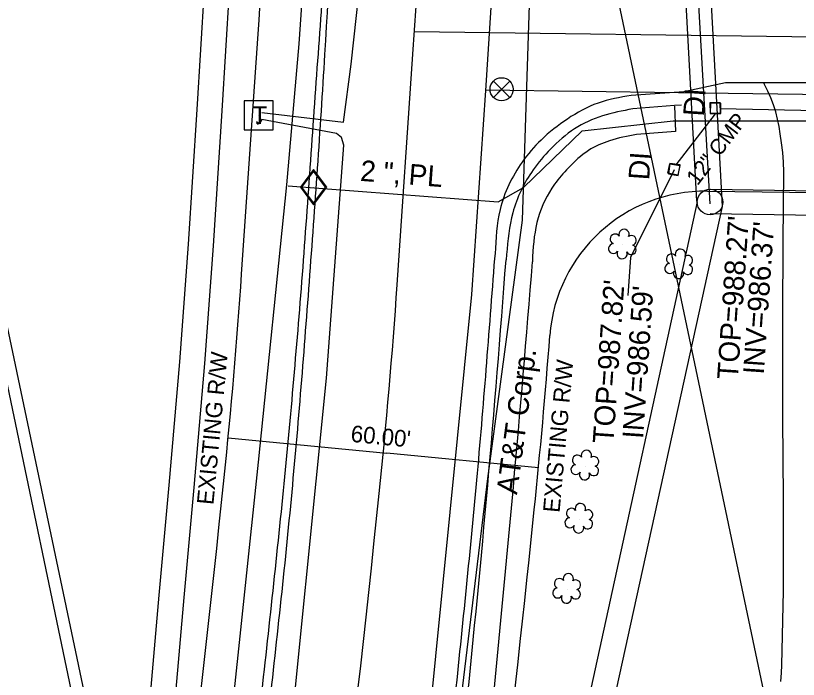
# Model space of a CAD drawing. Extents: x 1614427 to 1617186, y 896524 to 905462.
# Drawn here: x 1616608.8 to 1616759.4, y 901942.1 to 902069.8 of the extents above; entities that cross this region are included whole.
import ezdxf

# ---------------------------------------------------------------- set-up
doc = ezdxf.new("R2010")
doc.units = 0
for name, color, linetype in [('Exist Horizontal Alignment', 7, 'Continuous'), ('Exist Right of Way Line', 7, 'Continuous'), ('Exist Right of Way Line Text', 7, 'Continuous'), ('Exist Right of Way Width CELL', 7, 'Continuous'), ('Exist Roads Curbs', 7, 'Continuous'), ('Exist Roads EOP', 7, 'Continuous'), ('Exist Roads EOP Other', 7, 'Continuous'), ('Exist Roads EOT', 7, 'Continuous'), ('Exist Structure Minor Drop Inlet', 7, 'Continuous'), ('Exist Structure Minor Drop Inlet Leader', 7, 'Continuous'), ('Exist Structure Minor Drop Inlet Text', 7, 'Continuous'), ('Exist Structure Minor Drop Inlet Top Elevation', 7, 'Continuous'), ('Exist Structure Minor Pipes CMP 12 Inch', 7, 'Continuous'), ('Exist Structure Minor Pipes CMP 12 Inch Invert', 7, 'Continuous'), ('Exist Structure Minor Pipes CMP 12 Inch Text', 7, 'Continuous'), ('Exist Structure Minor Pipes RCP 12 Inch', 7, 'Continuous'), ('Exist Structure Minor Pipes RCP 12 Inch Invert', 7, 'Continuous'), ('Exist Utilities Gas UG Line SUE LOS B', 7, 'Continuous'), ('Exist Utilities Gas UG Line SUE LOS B Text', 7, 'Continuous'), ('Exist Utilities Gas Valve CELL', 7, 'Continuous'), ('Exist Utilities Other Pole CELL', 7, 'Continuous'), ('Exist Utilities Power UG Cable SUE LOS D', 7, 'Continuous'), ('Exist Utilities Telephone Pedestal CELL', 7, 'Continuous'), ('Exist Utilities Telephone UG Cable SUE LOS B', 7, 'Continuous'), ('Exist Utilities Telephone UG FO SUE LOS B', 7, 'Continuous'), ('Exist Utilities Telephone UG FO SUE LOS B Text', 7, 'Continuous'), ('Exist Utilities Telephone UG FO SUE LOS D', 7, 'Continuous'), ('Exist Utilities TV UG FO Cable SUE LOS D', 7, 'Continuous'), ('Exist Utilities Water UG Line SUE LOS B', 7, 'Continuous'), ('Exist Utilities Water Valve CELL', 7, 'Continuous'), ('Exist Vegetation Shrub CELL', 7, 'Continuous')]:
    doc.layers.add(name, color=color, linetype=linetype)

# ---------------------------------------------------------------- blocks, each defined once
blk = doc.blocks.new('EXIST UTILITIES WATER VALVE')
at = {"layer": 'Exist Utilities Water Valve CELL'}
blk.add_lwpolyline([(0.0315, 0.0315), (-0.0315, -0.0315), (0, 0), (0.0315, -0.0315), (-0.0315, 0.0315)], dxfattribs=at)
blk.add_circle((0, 0), 0.0445, dxfattribs=at)
blk = doc.blocks.new('EXIST UTILITIES GAS VALVE')
at = {"layer": 'Exist Utilities Gas Valve CELL'}
blk.add_line((0, 0), (0, 0), dxfattribs=at)
blk.add_lwpolyline([(0, 0.0683), (-0.0508, 0), (0, -0.0683), (0.0508, 0), (0, 0.0683)], dxfattribs=at)
blk.add_lwpolyline([(0.0458, 0), (0, 0.0615), (-0.0458, 0), (0, -0.0615)], close=True, dxfattribs=at)
blk = doc.blocks.new('EXIST UTILITIES TELEPHONE PEDESTAL')
at = {"layer": 'Exist Utilities Telephone Pedestal CELL'}
blk.add_line((0, 0), (0, 0), dxfattribs=at)
blk.add_lwpolyline([(-0.0545, -0.0565), (0.0574, -0.0565), (0.0574, 0.0554), (-0.0545, 0.0554), (-0.0545, -0.0565)], dxfattribs=at)
blk.add_text('T', height=0.0684, dxfattribs=at).set_placement((-0.0226, -0.0343))

msp = doc.modelspace()

# ---------------------------------------------------------------- linework, layer by layer
at = {"layer": 'Exist Horizontal Alignment'}
for p, q in [((1616685.54, 902066.8), (1616995.51, 902062.72)), ((1616682.21, 902018.06), (1616685.25, 902062.41)), ((1616677.74, 901968.22), (1616678.75, 901977.88))]:
    msp.add_line(p, q, dxfattribs=at)
for centre, radius, start, end in [((1614235.45, 902230.14), 2455.53, 356.08333, 2.98333), ((1615538.97, 902096.33), 1145.92, 354.06667, 356.08333), ((1613828.3, 902264.36), 2864.79, 348.01667, 354.06667)]:
    msp.add_arc(centre, radius, start, end, dxfattribs=at)
at = {"layer": 'Exist Right of Way Line'}
for p, q in [((1616010.65, 905462.23), (1616993.32, 900797.76)), ((1615887.44, 905426.15), (1616864.55, 900788.06)), ((1616652.28, 902020.11), (1616655.32, 902064.46)), ((1616741.9, 902036.05), (1616995.11, 902032.72)), ((1616647.9, 901971.32), (1616648.91, 901980.98)), ((1616707.58, 901965.12), (1616708.59, 901974.78))]:
    msp.add_line(p, q, dxfattribs=at)
for centre, radius, start, end in [((1614235.45, 902230.14), 2425.53, 356.08333, 2.98333), ((1616741.5, 902006.06), 30, 89.2466, 175.7066), ((1615538.97, 902096.33), 1115.92, 354.06667, 356.08333), ((1615538.97, 902096.33), 1175.92, 354.06667, 355.70658), ((1613828.3, 902264.36), 2834.79, 348.81938, 354.06667), ((1613828.3, 902264.36), 2894.79, 349.06983, 354.06667)]:
    msp.add_arc(centre, radius, start, end, dxfattribs=at)
at = {"layer": 'Exist Right of Way Width CELL'}
for p in [(1616649.67, 901988.6), (1616709.39, 901982.8)]:
    msp.add_line(p, (1616680.22, 901985.63), dxfattribs=at)
at = {"layer": 'Exist Roads Curbs'}
msp.add_line((1616703.26, 902023.89), (1616703.16, 902022.83), dxfattribs=at)
msp.add_lwpolyline([(1616736.91, 902052.58), (1616735.58, 902052.56), (1616727.54, 902051.89)], dxfattribs=at)
msp.add_ellipse((1613763.47, 902238.4), major_axis=(355.71, 2940.7), ratio=0.995075, start_param=4.729988, end_param=4.759334, dxfattribs=at)
msp.add_spline([(1616727.54, 902051.89), (1616721.72, 902050.55), (1616716.36, 902048.06), (1616711.73, 902044.16), (1616708.36, 902040.14), (1616704.47, 902031.9), (1616703.26, 902023.89)], degree=3, dxfattribs=at)
at = {"layer": 'Exist Roads EOP'}
msp.add_line((1616701.09, 902024.04), (1616700.93, 902023.09), dxfattribs=at)
msp.add_lwpolyline([(1616995.15, 902054.27), (1616961.48, 902054.78), (1616918.48, 902055.01), (1616876.42, 902055.6), (1616833.56, 902056.42), (1616793.91, 902056.9), (1616751.65, 902056.89), (1616745.38, 902056.89), (1616737.38, 902055.19), (1616727.24, 902054.46)], dxfattribs=at)
for points in [[(1616655.28, 901931.6), (1616660.06, 901975.76), (1616663.88, 902018.68), (1616667.04, 902062.5), (1616670.01, 902105.53), (1616671.54, 902149.52), (1616672.6, 902193.68), (1616673.08, 902239.26), (1616672.8, 902282.74), (1616671, 902328.37), (1616668.63, 902372.54), (1616666.77, 902402.14), (1616664.33, 902433.03)], [(1616727.24, 902054.46), (1616720.86, 902053.02), (1616714.96, 902049.94), (1616709.89, 902045.9), (1616706.27, 902041.66), (1616702, 902032.51), (1616701.09, 902024.04)], [(1616700.93, 902023.09), (1616697.48, 901980.45), (1616693.1, 901936.47), (1616691.15, 901917.39), (1616689.48, 901902.09), (1616684.13, 901861.58), (1616677.6, 901820.03), (1616673.54, 901794.89), (1616668.88, 901768.87), (1616663.9, 901741.21), (1616658.75, 901714.99)]]:
    msp.add_spline(points, degree=3, dxfattribs=at)
at = {"layer": 'Exist Roads EOP Other'}
msp.add_line((1616708.24, 902023.52), (1616708.26, 902022.46), dxfattribs=at)
for points in [[(1616612.82, 901802.9), (1616617.67, 901825.43), (1616622.38, 901847.22), (1616626.49, 901866.61), (1616627.92, 901872.98), (1616628.44, 901875.07), (1616628.88, 901877.18), (1616629.24, 901879.31), (1616629.52, 901881.45), (1616629.72, 901883.51), (1616630.6, 901891.66), (1616631.35, 901901.23), (1616633.18, 901919.93), (1616634.76, 901939.16), (1616636.44, 901958.33), (1616638.35, 901979.47), (1616640.39, 902003.25), (1616642.08, 902025.89), (1616643.74, 902051.78), (1616645.12, 902074.94)], [(1616617.51, 901801.89), (1616622.36, 901824.42), (1616627.07, 901846.22), (1616631.18, 901865.59), (1616632.59, 901871.88), (1616633.12, 901874.01), (1616633.59, 901876.29), (1616633.98, 901878.59), (1616634.29, 901880.9), (1616634.5, 901883.02), (1616635.38, 901891.22), (1616636.14, 901900.81), (1616637.96, 901919.5), (1616639.54, 901938.75), (1616641.22, 901957.9), (1616643.14, 901979.05), (1616645.17, 902002.87), (1616646.87, 902025.55), (1616648.53, 902051.49), (1616649.92, 902074.68)], [(1616756.03, 901941.69), (1616756.17, 901943.36), (1616756.23, 901944.88), (1616756.53, 901959.19), (1616756.57, 901976.99), (1616756.44, 901992.33), (1616756.4, 902011.96), (1616756.5, 902026.37), (1616756.64, 902039.75), (1616756.57, 902041.62), (1616756.42, 902043.49), (1616756.19, 902045.34), (1616755.89, 902047.09), (1616755.7, 902048.51), (1616755.43, 902049.91), (1616755.07, 902051.3), (1616754.65, 902052.66), (1616754.14, 902054), (1616753.57, 902055.31), (1616752.92, 902056.58), (1616752.82, 902056.77)], [(1616735.56, 902052.4), (1616735.79, 902047.54), (1616728.27, 902046.98)]]:
    msp.add_lwpolyline(points, dxfattribs=at)
msp.add_ellipse((1612721.96, 902335.52), major_axis=(418.09, 4102.81), ratio=0.969558, start_param=4.713779, end_param=4.734862, dxfattribs=at)
msp.add_spline([(1616728.27, 902046.98), (1616723.09, 902045.76), (1616719.03, 902043.88), (1616715.16, 902040.56), (1616712.51, 902037.38), (1616709.33, 902030.9), (1616708.24, 902023.52)], degree=3, dxfattribs=at)
at = {"layer": 'Exist Roads EOT'}
msp.add_spline([(1616657.03, 901931.53), (1616661.72, 901975.47), (1616665.32, 902018.62), (1616668.31, 902062.36), (1616670.59, 902105.52), (1616672.4, 902149.47), (1616673.48, 902193.66), (1616673.75, 902239.27), (1616673.47, 902282.77), (1616672.23, 902328.42), (1616670.01, 902372.56), (1616668.01, 902402.36), (1616665.45, 902433.28)], degree=3, dxfattribs=at)
at = {"layer": 'Exist Structure Minor Drop Inlet'}
for points in [[(1616744.34, 902051.01), (1616742.48, 902050.98), (1616742.45, 902053.11), (1616744.31, 902053.13)], [(1616736.24, 902039.14), (1616734.32, 902039.51), (1616734.66, 902041.33), (1616736.59, 902040.97)]]:
    msp.add_lwpolyline(points, close=True, dxfattribs=at)
for points in [[(1616744.49, 902052.96), (1616742.48, 902052.99), (1616742.45, 902051), (1616744.51, 902051.03), (1616744.49, 902052.96)], [(1616736.65, 902041.11), (1616734.69, 902041.41), (1616734.44, 902039.42), (1616736.31, 902039.1), (1616736.65, 902041.11)]]:
    msp.add_lwpolyline(points, dxfattribs=at)
at = {"layer": 'Exist Structure Minor Drop Inlet Leader'}
msp.add_lwpolyline([(1616735.52, 902040.19), (1616727.1, 902023.27), (1616726.59, 902015.96)], dxfattribs=at)
at = {"layer": 'Exist Structure Minor Pipes CMP 12 Inch'}
msp.add_line((1616743.41, 902050.96), (1616735.84, 902041.1), dxfattribs=at)
msp.add_line((1616743.41, 902050.96), (1616735.84, 902041.1), dxfattribs=at)
at = {"layer": 'Exist Structure Minor Pipes RCP 12 Inch'}
msp.add_line((1616860.49, 902049.55), (1616744.38, 902051.9), dxfattribs=at)
msp.add_line((1616860.49, 902049.55), (1616744.38, 902051.9), dxfattribs=at)
at = {"layer": 'Exist Utilities Gas UG Line SUE LOS B'}
for points in [[(1616661.01, 902037.25), (1616663.33, 902064.4), (1616667.18, 902120.35), (1616669.8, 902175.63), (1616670.18, 902203.89), (1616670, 902252.83), (1616667.06, 902308.42), (1616666.18, 902342.89), (1616662.96, 902384.82), (1616659.36, 902418.53), (1616657.17, 902446.04), (1616652.37, 902490.94), (1616648.49, 902520.82), (1616640.31, 902575.63), (1616630.24, 902629.08), (1616624.64, 902659), (1616610.54, 902718.34), (1616603.5, 902747.83), (1616594.95, 902779.96), (1616588.83, 902805.4), (1616574.94, 902856.71)], [(1616661.26, 902037.09), (1616701.66, 902034.02), (1616706.49, 902036.74), (1616717.78, 902047.67), (1616735.33, 902049.61), (1616770.19, 902049.58), (1616867.38, 902046.05), (1616915.48, 902044.83), (1616973.65, 902045.68), (1616984.64, 902045.63)], [(1616538.79, 901324.29), (1616552.84, 901386.17), (1616571.68, 901471.14), (1616584.04, 901531.54), (1616593.62, 901586.74), (1616603.9, 901635.05), (1616614.54, 901699.5), (1616631.36, 901792.12), (1616640.8, 901853.71), (1616647.39, 901906.62), (1616655.55, 901983.89), (1616661.01, 902037.25)]]:
    msp.add_lwpolyline(points, dxfattribs=at)
at = {"layer": 'Exist Utilities Other Pole CELL'}
msp.add_circle((1616742.43, 902033.97), 2.46, dxfattribs=at)
at = {"layer": 'Exist Utilities Power UG Cable SUE LOS D'}
for p, q in [((1616739.9, 902034.14), (1616729.53, 902223.32)), ((1617047.28, 902027.07), (1616742.46, 902031.7))]:
    msp.add_line(p, q, dxfattribs=at)
msp.add_lwpolyline([(1616667.35, 901702.61), (1616628.62, 901896.27), (1616578.22, 902137.47), (1616526.22, 902383.26), (1616717.86, 902408.9)], dxfattribs=at)
at = {"layer": 'Exist Utilities Telephone UG Cable SUE LOS B'}
for points in [[(1616656.18, 902051.21), (1616671.87, 902049.35), (1616673.37, 902060.47), (1616677.62, 902099.17), (1616679.56, 902131), (1616682.04, 902274.91), (1616677.66, 902369.06), (1616673.54, 902414.87), (1616672.97, 902415.98), (1616670.64, 902416.97), (1616666.17, 902416.66), (1616663.13, 902416.28), (1616653.85, 902415.38)], [(1616586.65, 901614.7), (1616592.7, 901627.45), (1616597.67, 901647), (1616601.16, 901647.82), (1616608.45, 901646.9), (1616613.6, 901651.99), (1616633.98, 901750.98), (1616649.47, 901834.39), (1616660.58, 901920.16), (1616668.64, 902000.09), (1616671.96, 902044.94), (1616671.51, 902046.39), (1616670.53, 902047.17), (1616656.18, 902049.88), (1616655.65, 902049.04), (1616655.13, 902049.4), (1616655.43, 902048.87), (1616655.12, 902049.21)]]:
    msp.add_lwpolyline(points, dxfattribs=at)
at = {"layer": 'Exist Utilities Telephone UG FO SUE LOS B'}
msp.add_lwpolyline([(1616583, 901316.53), (1616602.93, 901389.19), (1616611.41, 901436.2), (1616627.53, 901512.28), (1616643.11, 901593.04), (1616647.49, 901611.03), (1616645.52, 901612.27), (1616650.47, 901635.14), (1616653.42, 901650.24), (1616659.31, 901688.22), (1616659.33, 901688.62), (1616660.8, 901715.96), (1616675.12, 901794.59), (1616685.37, 901862.2), (1616699.64, 901980.75), (1616706.3, 902030.47), (1616708.52, 902097.65)], dxfattribs=at)
at = {"layer": 'Exist Utilities Telephone UG FO SUE LOS D'}
msp.add_line((1617047.43, 902032.03), (1616742.6, 902036.38), dxfattribs=at)
msp.add_lwpolyline([(1616672.21, 901702.3), (1616744.81, 902033.13), (1616734.48, 902223.1)], dxfattribs=at)
at = {"layer": 'Exist Utilities TV UG FO Cable SUE LOS D'}
msp.add_line((1616667.68, 901702.75), (1616739.98, 902034.01), dxfattribs=at)
msp.add_lwpolyline([(1616742.45, 902033.61), (1616731.67, 902222.81), (1616717.86, 902408.9), (1616693.14, 902610.5), (1616650.43, 902782.74), (1616615.07, 902920.36)], dxfattribs=at)
at = {"layer": 'Exist Utilities Water UG Line SUE LOS B'}
for points in [[(1616682.85, 901889.35), (1616688.26, 901932.45), (1616696.61, 902016.19), (1616699.26, 902055.42), (1616702.78, 902110.39), (1616705.34, 902181.72), (1616707.31, 902255.35), (1616706.62, 902316.75), (1616703.14, 902377.45), (1616699.12, 902434.84), (1616686.86, 902524.85), (1616669.78, 902622.34), (1616658.13, 902681.62), (1616634.87, 902784.56), (1616617.17, 902853.52), (1616602.15, 902900.61), (1616584.28, 902954.24), (1616571.86, 902993.81)], [(1616682.85, 901889.35), (1616688.26, 901932.45), (1616696.61, 902016.19), (1616699.26, 902055.42), (1616702.78, 902110.39), (1616705.34, 902181.72), (1616707.31, 902255.35), (1616706.62, 902316.75), (1616703.14, 902377.45), (1616699.12, 902434.84), (1616686.86, 902524.85), (1616669.78, 902622.34), (1616658.13, 902681.62), (1616634.87, 902784.56), (1616617.17, 902853.52), (1616602.15, 902900.61), (1616584.28, 902954.24), (1616571.86, 902993.81)], [(1616699.3, 902055.58), (1616736.36, 902055.02), (1616812.77, 902054.01), (1616869.09, 902053.9), (1616943.18, 902052.9), (1616985.1, 902052.35)]]:
    msp.add_lwpolyline(points, dxfattribs=at)
at = {"layer": 'Exist Vegetation Shrub CELL'}
for p, q in [((1616725.63, 902025.71), (1616725.63, 902025.71)), ((1616736.48, 902021.89), (1616736.48, 902021.89)), ((1616718.4, 901983.18), (1616718.4, 901983.18)), ((1616717.25, 901972.95), (1616717.25, 901972.95)), ((1616714.91, 901959.45), (1616714.91, 901959.45))]:
    msp.add_line(p, q, dxfattribs=at)
for centre, radius, start, end in [((1616725.86, 902027.75), 0.99, 334.8391, 200.4717), ((1616724.15, 902026.84), 0.968, 35.8908, 245.4216), ((1616727.31, 902026.58), 0.929, 284.4567, 126.0861), ((1616723.83, 902025.01), 0.955, 95.1099, 327.9534), ((1616725.5, 902024.03), 0.984, 151.2797, 21.387), ((1616727.27, 902024.78), 0.937, 204.9913, 73.4601), ((1616736.71, 902023.93), 0.99, 334.8391, 200.4717), ((1616735, 902023.02), 0.968, 35.8908, 245.4216), ((1616738.15, 902022.76), 0.929, 284.4567, 126.0861), ((1616734.68, 902021.19), 0.955, 95.1099, 327.9534), ((1616738.12, 902020.96), 0.937, 204.9913, 73.4601), ((1616736.35, 902020.21), 0.984, 151.2797, 21.387), ((1616716.91, 901984.31), 0.968, 35.8908, 245.4216), ((1616718.62, 901985.22), 0.99, 334.8391, 200.4717), ((1616720.07, 901984.05), 0.929, 284.4567, 126.0861), ((1616716.6, 901982.48), 0.955, 95.1099, 327.9534), ((1616720.03, 901982.25), 0.937, 204.9913, 73.4601), ((1616718.27, 901981.5), 0.984, 151.2797, 21.387), ((1616715.76, 901974.08), 0.968, 35.8908, 245.4216), ((1616717.47, 901974.99), 0.99, 334.8391, 200.4717), ((1616718.92, 901973.82), 0.929, 284.4567, 126.0861), ((1616715.44, 901972.25), 0.955, 95.1099, 327.9534), ((1616717.12, 901971.27), 0.984, 151.2797, 21.387), ((1616718.88, 901972.02), 0.937, 204.9913, 73.4601), ((1616715.14, 901961.49), 0.99, 334.8391, 200.4717), ((1616713.43, 901960.57), 0.968, 35.8908, 245.4216), ((1616716.58, 901960.32), 0.929, 284.4567, 126.0861), ((1616713.11, 901958.74), 0.955, 95.1099, 327.9534), ((1616714.78, 901957.76), 0.984, 151.2797, 21.387), ((1616716.55, 901958.52), 0.937, 204.9913, 73.4601)]:
    msp.add_arc(centre, radius, start, end, dxfattribs=at)

# ---------------------------------------------------------------- block references
at = {"layer": 'Exist Utilities Gas Valve CELL', "xscale": 50, "yscale": 50}
msp.add_blockref('EXIST UTILITIES GAS VALVE', (1616666.12, 902036.84), dxfattribs=at)
at = {"layer": 'Exist Utilities Telephone Pedestal CELL', "xscale": 50, "yscale": 50}
msp.add_blockref('EXIST UTILITIES TELEPHONE PEDESTAL', (1616655.51, 902050.7), dxfattribs=at)
at = {"layer": 'Exist Utilities Water Valve CELL', "xscale": 50, "yscale": 50}
msp.add_blockref('EXIST UTILITIES WATER VALVE', (1616702.31, 902055.67), dxfattribs=at)

# ---------------------------------------------------------------- texts
at = {"layer": 'Exist Right of Way Line Text'}
for rotation, p in [(84.5988, (1616646.84, 901975.62)), (84.8301, (1616713.45, 901974.11))]:
    msp.add_text('EXISTING R/W', height=3.2, rotation=rotation, dxfattribs=at).set_placement(p)
at = {"layer": 'Exist Right of Way Width CELL'}
msp.add_text("60.00'", height=3.2, rotation=354.4596, dxfattribs=at).set_placement((1616673.17, 901987.85))
at = {"layer": 'Exist Structure Minor Drop Inlet Text'}
for p in [(1616741.22, 902050.36), (1616730.7, 902038.11)]:
    msp.add_text('DI', height=4, rotation=86.0833, dxfattribs=at).set_placement(p)
at = {"layer": 'Exist Structure Minor Drop Inlet Top Elevation'}
for s, p in [("TOP=988.27'", (1616747.76, 901999.71)), ("TOP=987.82'", (1616723.82, 901987.42))]:
    msp.add_text(s, height=4, rotation=86.0833, dxfattribs=at).set_placement(p)
at = {"layer": 'Exist Structure Minor Pipes CMP 12 Inch Invert'}
msp.add_text("INV=986.59'", height=4, rotation=86.0833, dxfattribs=at).set_placement((1616729.53, 901988.33))
at = {"layer": 'Exist Structure Minor Pipes CMP 12 Inch Text'}
msp.add_text('12" CMP', height=3, rotation=52.5059, dxfattribs=at).set_placement((1616740.01, 902036.99))
at = {"layer": 'Exist Structure Minor Pipes RCP 12 Inch Invert'}
msp.add_text("INV=986.37'", height=4, rotation=86.0833, dxfattribs=at).set_placement((1616752.76, 902000.7))
at = {"layer": 'Exist Utilities Gas UG Line SUE LOS B Text'}
msp.add_text('2 ", PL', height=4, rotation=355.6512, dxfattribs=at).set_placement((1616675, 902038.05))
at = {"layer": 'Exist Utilities Telephone UG FO SUE LOS B Text'}
msp.add_text('AT&T Corp.', height=4, rotation=82.3617, dxfattribs=at).set_placement((1616705.26, 901977.57))

doc.saveas('drawing.dxf')
